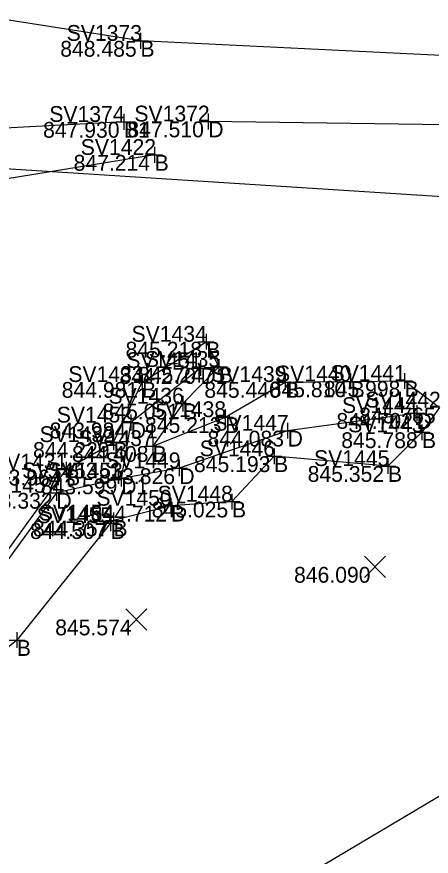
# Model space of a CAD drawing. Extents: x 2125299 to 2129212, y 713100 to 714300.
# Drawn here: x 2128355.4 to 2128381.6, y 713842.2 to 713895.2 of the extents above; entities that cross this region are included whole.
import ezdxf

# ---------------------------------------------------------------- set-up
doc = ezdxf.new("R2010")
doc.units = 0
for name, color, linetype in [('DR_X_Ditch', 7, 'Continuous'), ('RD_X_Fence', 7, 'Continuous'), ('RW_P_Esmt_TMP', 7, 'Continuous'), ('RW_X_Esmt_CH', 7, 'Continuous'), ('RW_X_Fee_WL', 7, 'Continuous'), ('SV_X_Break_Lines', 7, 'Continuous'), ('SV_X_Mon_Cells_Found', 7, 'Continuous'), ('SV_X_Text_Elevation', 7, 'Continuous')]:
    doc.layers.add(name, color=color, linetype=linetype)

msp = doc.modelspace()

# ---------------------------------------------------------------- linework, layer by layer
at = {"layer": 'DR_X_Ditch'}
for points in [[(2128604.481, 713972.859), (2128563.259, 713957.895), (2128524.583, 713946.255), (2128524.597, 713946.253), (2128472.88, 713922.441), (2128453.797, 713914.261), (2128410.953, 713892.601), (2128396.045, 713888.223), (2128367.499, 713888.623)], [(2128367.002, 713873.039), (2128362.594, 713869.592), (2128361.997, 713866.06)], [(2128380.672, 713870.195), (2128372.514, 713869.076), (2128365.668, 713866.704), (2128361.997, 713866.06), (2128357.9, 713865.15), (2128354.295, 713860.223), (2128351.441, 713856.512), (2128347.904, 713853.274), (2128346.806, 713850.533)]]:
    msp.add_lwpolyline(points, dxfattribs=at)
at = {"layer": 'RD_X_Fence'}
msp.add_lwpolyline([(2128620.57, 713921.414), (2128582.003, 713911.258), (2128527.9, 713897.049), (2128485.218, 713885.694), (2128444.136, 713879.079), (2128410.256, 713882.079), (2128351.04, 713885.853)], dxfattribs=at)
at = {"layer": 'SV_X_Break_Lines'}
msp.add_line((2128362.17, 713888.596), (2128362.17, 713888.596), dxfattribs=at)
for points in [[(2128473.365, 713923.912), (2128453.453, 713915.843), (2128410.188, 713893.98), (2128387.409, 713892.535), (2128363.211, 713893.719), (2128345.595, 713896.5), (2128318.819, 713891.258), (2128295.116, 713880.906), (2128274.488, 713885.799), (2128242.12, 713879.196), (2128218.829, 713874.939), (2128184.367, 713862.099), (2128151.548, 713852.787), (2128121.592, 713848.655), (2128121.634, 713848.486), (2128085.287, 713843.491), (2128066.442, 713838.356)], [(2128362.17, 713888.596), (2128349.078, 713887.908), (2128324.526, 713881.58), (2128301.553, 713867.571), (2128295.426, 713864.02), (2128280.273, 713864.928), (2128247.092, 713854.317), (2128208.777, 713841.528), (2128155.39, 713832.168), (2128105.372, 713824.737)], [(2128364.108, 713886.51), (2128353.616, 713884.817)], [(2128352.748, 713858.655), (2128358.51, 713866.616), (2128361.507, 713868.357), (2128363.316, 713872.155), (2128367.368, 713874.702), (2128368.158, 713873.106), (2128365.897, 713870.786), (2128363.985, 713868.106), (2128368.562, 713869.934), (2128372.364, 713872.155), (2128376.494, 713872.192), (2128379.904, 713872.221), (2128382.103, 713870.541), (2128381.002, 713868.975), (2128378.852, 713866.843), (2128371.657, 713867.462), (2128368.993, 713864.596), (2128365.138, 713864.337), (2128361.507, 713863.4), (2128361.328, 713863.233), (2128355.396, 713855.844), (2128350.477, 713851.799)], [(2128285.007, 713846.966), (2128304.036, 713841.037), (2128326.028, 713831.967), (2128335.229, 713829.953), (2128351.209, 713834.175), (2128372.654, 713840.365), (2128397.041, 713854.87), (2128424.528, 713863.803), (2128437.965, 713867.069)]]:
    msp.add_lwpolyline(points, dxfattribs=at)
at = {"layer": 'SV_X_Mon_Cells_Found'}
for p, q in [((2128363.211, 713894.219), (2128363.211, 713893.219)), ((2128362.711, 713893.719), (2128363.711, 713893.719)), ((2128363.211, 713893.719), (2128363.211, 713893.719)), ((2128362.17, 713889.096), (2128362.17, 713888.096)), ((2128367.499, 713889.123), (2128367.499, 713888.123)), ((2128361.67, 713888.596), (2128362.67, 713888.596)), ((2128362.17, 713888.596), (2128362.17, 713888.596)), ((2128366.999, 713888.623), (2128367.999, 713888.623)), ((2128367.499, 713888.623), (2128367.499, 713888.623)), ((2128364.108, 713887.01), (2128364.108, 713886.01)), ((2128363.608, 713886.51), (2128364.608, 713886.51)), ((2128364.108, 713886.51), (2128364.108, 713886.51)), ((2128367.368, 713875.202), (2128367.368, 713874.202)), ((2128366.868, 713874.702), (2128367.868, 713874.702)), ((2128367.368, 713874.702), (2128367.368, 713874.702)), ((2128367.002, 713873.539), (2128367.002, 713872.539)), ((2128368.158, 713873.606), (2128368.158, 713872.606)), ((2128363.316, 713872.655), (2128363.316, 713871.655)), ((2128366.502, 713873.039), (2128367.502, 713873.039)), ((2128367.002, 713873.039), (2128367.002, 713873.039)), ((2128367.658, 713873.106), (2128368.658, 713873.106)), ((2128368.158, 713873.106), (2128368.158, 713873.106)), ((2128372.364, 713872.655), (2128372.364, 713871.655)), ((2128376.494, 713872.692), (2128376.494, 713871.692)), ((2128379.904, 713872.721), (2128379.904, 713871.721)), ((2128362.816, 713872.155), (2128363.816, 713872.155)), ((2128363.316, 713872.155), (2128363.316, 713872.155)), ((2128371.864, 713872.155), (2128372.864, 713872.155)), ((2128372.364, 713872.155), (2128372.364, 713872.155)), ((2128375.994, 713872.192), (2128376.994, 713872.192)), ((2128376.494, 713872.192), (2128376.494, 713872.192)), ((2128379.404, 713872.221), (2128380.404, 713872.221)), ((2128379.904, 713872.221), (2128379.904, 713872.221)), ((2128365.897, 713871.286), (2128365.897, 713870.286)), ((2128365.397, 713870.786), (2128366.397, 713870.786)), ((2128365.897, 713870.786), (2128365.897, 713870.786)), ((2128380.672, 713870.695), (2128380.672, 713869.695)), ((2128362.594, 713870.092), (2128362.594, 713869.092)), ((2128368.562, 713870.434), (2128368.562, 713869.434)), ((2128380.172, 713870.195), (2128381.172, 713870.195)), ((2128380.672, 713870.195), (2128380.672, 713870.195)), ((2128362.094, 713869.592), (2128363.094, 713869.592)), ((2128362.594, 713869.592), (2128362.594, 713869.592)), ((2128368.062, 713869.934), (2128369.062, 713869.934)), ((2128368.562, 713869.934), (2128368.562, 713869.934)), ((2128372.514, 713869.576), (2128372.514, 713868.576)), ((2128381.002, 713869.475), (2128381.002, 713868.475)), ((2128372.014, 713869.076), (2128373.014, 713869.076)), ((2128372.514, 713869.076), (2128372.514, 713869.076)), ((2128380.502, 713868.975), (2128381.502, 713868.975)), ((2128381.002, 713868.975), (2128381.002, 713868.975)), ((2128361.507, 713868.857), (2128361.507, 713867.857)), ((2128363.985, 713868.606), (2128363.985, 713867.606)), ((2128361.007, 713868.357), (2128362.007, 713868.357)), ((2128361.507, 713868.357), (2128361.507, 713868.357)), ((2128363.485, 713868.106), (2128364.485, 713868.106)), ((2128363.985, 713868.106), (2128363.985, 713868.106)), ((2128371.657, 713867.962), (2128371.657, 713866.962)), ((2128371.157, 713867.462), (2128372.157, 713867.462)), ((2128371.657, 713867.462), (2128371.657, 713867.462)), ((2128378.852, 713867.343), (2128378.852, 713866.343)), ((2128358.51, 713867.116), (2128358.51, 713866.116)), ((2128365.668, 713867.204), (2128365.668, 713866.204)), ((2128378.352, 713866.843), (2128379.352, 713866.843)), ((2128378.852, 713866.843), (2128378.852, 713866.843)), ((2128358.01, 713866.616), (2128359.01, 713866.616)), ((2128358.51, 713866.616), (2128358.51, 713866.616)), ((2128361.997, 713866.56), (2128361.997, 713865.56)), ((2128361.997, 713866.56), (2128361.997, 713865.56)), ((2128365.168, 713866.704), (2128366.168, 713866.704)), ((2128365.668, 713866.704), (2128365.668, 713866.704)), ((2128361.497, 713866.06), (2128362.497, 713866.06)), ((2128361.497, 713866.06), (2128362.497, 713866.06)), ((2128361.997, 713866.06), (2128361.997, 713866.06)), ((2128361.997, 713866.06), (2128361.997, 713866.06)), ((2128357.9, 713865.65), (2128357.9, 713864.65)), ((2128357.4, 713865.15), (2128358.4, 713865.15)), ((2128357.9, 713865.15), (2128357.9, 713865.15)), ((2128365.138, 713864.837), (2128365.138, 713863.837)), ((2128368.993, 713865.096), (2128368.993, 713864.096)), ((2128364.638, 713864.337), (2128365.638, 713864.337)), ((2128365.138, 713864.337), (2128365.138, 713864.337)), ((2128368.493, 713864.596), (2128369.493, 713864.596)), ((2128368.993, 713864.596), (2128368.993, 713864.596)), ((2128361.328, 713863.733), (2128361.328, 713862.733)), ((2128361.507, 713863.9), (2128361.507, 713862.9)), ((2128360.828, 713863.233), (2128361.828, 713863.233)), ((2128361.007, 713863.4), (2128362.007, 713863.4)), ((2128361.328, 713863.233), (2128361.328, 713863.233)), ((2128361.507, 713863.4), (2128361.507, 713863.4)), ((2128355.396, 713856.344), (2128355.396, 713855.344)), ((2128354.896, 713855.844), (2128355.896, 713855.844)), ((2128355.396, 713855.844), (2128355.396, 713855.844))]:
    msp.add_line(p, q, dxfattribs=at)
at = {"layer": 'SV_X_Text_Elevation'}
for p, q in [((2128377.365, 713859.801), (2128378.699, 713861.136)), ((2128377.365, 713861.136), (2128378.699, 713859.801)), ((2128362.277, 713856.475), (2128363.611, 713857.81)), ((2128362.277, 713857.81), (2128363.611, 713856.475))]:
    msp.add_line(p, q, dxfattribs=at)

# ---------------------------------------------------------------- texts
at = {"layer": 'RW_P_Esmt_TMP'}
for s, p in [('B', (2128363.211, 713892.719)), ('B1', (2128362.17, 713887.596)), ('D', (2128367.499, 713887.623)), ('B', (2128364.108, 713885.51)), ('B', (2128367.368, 713873.702)), ('D1', (2128367.002, 713872.039)), ('B', (2128368.158, 713872.106)), ('B', (2128363.316, 713871.155)), ('B', (2128372.364, 713871.155)), ('B', (2128376.494, 713871.192)), ('B', (2128379.904, 713871.221)), ('B', (2128365.897, 713869.786)), ('D', (2128380.672, 713869.195)), ('D1', (2128362.594, 713868.592)), ('B', (2128368.562, 713868.934)), ('D', (2128372.514, 713868.076)), ('B', (2128381.002, 713867.975)), ('B', (2128361.507, 713867.357)), ('B', (2128363.985, 713867.106)), ('B', (2128371.657, 713866.462)), ('B', (2128378.852, 713865.843)), ('B', (2128358.51, 713865.616)), ('D', (2128365.668, 713865.704)), ('D1', (2128361.997, 713865.06)), ('D', (2128361.997, 713865.06)), ('D', (2128357.9, 713864.15)), ('B', (2128365.138, 713863.337)), ('B', (2128368.993, 713863.596)), ('B', (2128361.328, 713862.233)), ('B', (2128361.507, 713862.4)), ('B', (2128355.396, 713854.844))]:
    msp.add_text(s, height=1, dxfattribs=at).set_placement(p)
at = {"layer": 'RW_X_Esmt_CH'}
for s, p in [('SV1373', (2128358.549, 713893.719)), ('SV1374', (2128357.45, 713888.596)), ('SV1372', (2128362.828, 713888.623)), ('SV1422', (2128359.437, 713886.51)), ('SV1434', (2128362.648, 713874.702)), ('SV1451', (2128362.322, 713873.039)), ('SV1435', (2128363.489, 713873.106)), ('SV1433', (2128358.654, 713872.155)), ('SV1439', (2128367.682, 713872.155)), ('SV1440', (2128371.782, 713872.192)), ('SV1441', (2128375.224, 713872.221)), ('SV1436', (2128361.195, 713870.786)), ('SV1442', (2128377.432, 713870.541)), ('SV1444', (2128375.952, 713870.195)), ('SV1452', (2128357.923, 713869.592)), ('SV1438', (2128363.863, 713869.934)), ('SV1447', (2128367.82, 713869.076)), ('SV1443', (2128376.34, 713868.975)), ('SV1432', (2128356.836, 713868.357)), ('SV1437', (2128359.291, 713868.106)), ('SV1446', (2128366.955, 713867.462)), ('SV1445', (2128374.183, 713866.843)), ('SV1431', (2128353.83, 713866.616)), ('SV1449', (2128360.986, 713866.704)), ('SV1453_1', (2128355.734, 713866.06)), ('SV1453', (2128357.335, 713866.06)), ('SV1457', (2128353.206, 713865.15)), ('SV1450', (2128360.426, 713864.337)), ('SV1448', (2128364.294, 713864.596)), ('SV1455', (2128356.659, 713863.233)), ('SV1454', (2128356.787, 713863.4))]:
    msp.add_text(s, height=1, dxfattribs=at).set_placement(p)
at = {"layer": 'RW_X_Fee_WL'}
for s, p in [('848.485', (2128358.141, 713892.719)), ('847.930', (2128357.056, 713887.596)), ('847.510', (2128362.385, 713887.623)), ('847.214', (2128358.986, 713885.51)), ('845.218', (2128362.268, 713873.702)), ('844.270', (2128361.888, 713872.039)), ('845.247', (2128363.062, 713872.106)), ('844.981', (2128358.234, 713871.155)), ('845.440', (2128367.25, 713871.155)), ('845.810', (2128371.38, 713871.192)), ('845.998', (2128374.804, 713871.221)), ('845.051', (2128360.815, 713869.786)), ('845.765', (2128377.033, 713869.541)), ('844.702', (2128375.599, 713869.195)), ('843.984', (2128357.472, 713868.592)), ('845.213', (2128363.498, 713868.934)), ('844.083', (2128367.45, 713868.076)), ('845.788', (2128375.902, 713867.975)), ('844.229', (2128356.423, 713867.357)), ('844.408', (2128358.885, 713867.106)), ('845.193', (2128366.593, 713866.462)), ('845.352', (2128373.779, 713865.843)), ('843.964', (2128353.388, 713865.616)), ('843.826', (2128360.564, 713865.704)), ('843.599', (2128356.913, 713865.06)), ('843.599', (2128356.913, 713865.06)), ('843.332', (2128352.827, 713864.15)), ('844.712', (2128360.065, 713863.337)), ('845.025', (2128363.923, 713863.596)), ('844.507', (2128356.232, 713862.233)), ('844.357', (2128356.411, 713862.4)), ('846.090', (2128372.918, 713859.469)), ('845.574', (2128357.822, 713856.143))]:
    msp.add_text(s, height=1, dxfattribs=at).set_placement(p)

doc.saveas('drawing.dxf')
